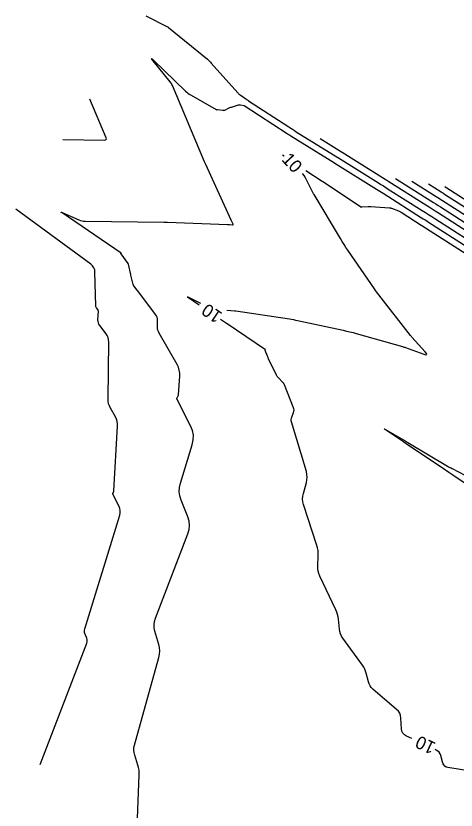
# Model space of a CAD drawing. Extents: x 1797789 to 1803805, y 249066 to 250293.
# Drawn here: x 1797804.6 to 1798010.2, y 249881.5 to 250253 of the extents above; entities that cross this region are included whole.
import ezdxf

# ---------------------------------------------------------------- set-up
doc = ezdxf.new("R2010")
doc.units = 0
doc.layers.add('33', color=7, linetype='Continuous')
doc.layers.add('34', color=7, linetype='Continuous')

msp = doc.modelspace()

# ---------------------------------------------------------------- linework, layer by layer
at = {"layer": '33'}
for points in [[(1797929.68, 250187.48), (1797929.31, 250187.81), (1797929.13, 250187.99), (1797929.08, 250188.07), (1797929.16, 250188.03), (1797929.38, 250187.9), (1797929.81, 250187.61)], [(1797903.13, 250115.46), (1797906.85, 250115.12), (1797906.88, 250115.11), (1797906.92, 250115.11), (1797906.96, 250115.1), (1797907, 250115.1), (1797907.23, 250115.07), (1797907.24, 250115.07), (1797932.35, 250111.26), (1797933.3, 250111.1), (1797934.25, 250110.94), (1797935.19, 250110.76), (1797936.13, 250110.56), (1797957.51, 250105.97), (1797959.03, 250105.62), (1797960.55, 250105.26), (1797962.07, 250104.87), (1797963.58, 250104.45), (1797985.12, 250098.34), (1797985.49, 250098.23), (1797985.86, 250098.12), (1797986.22, 250098), (1797986.59, 250097.87), (1797995.09, 250094.83), (1797996.06, 250094.56), (1797996.5, 250094.65), (1797996.41, 250095.09), (1797995.8, 250095.89), (1797989.57, 250102.82), (1797989.41, 250103), (1797989.25, 250103.18), (1797989.1, 250103.37), (1797988.95, 250103.56), (1797974.11, 250122.5), (1797973.57, 250123.19), (1797973.05, 250123.89), (1797972.54, 250124.59), (1797972.05, 250125.31), (1797959.66, 250143.41), (1797958.76, 250144.75), (1797957.87, 250146.11), (1797957.01, 250147.48), (1797956.17, 250148.86), (1797943.84, 250169.47), (1797943.82, 250169.51), (1797943.81, 250169.54), (1797943.79, 250169.57), (1797943.77, 250169.61), (1797943.65, 250169.81), (1797943.65, 250169.81), (1797939.63, 250177.53), (1797939.17, 250178.33), (1797938.64, 250179.08), (1797938.47, 250179.28)], [(1797940.07, 250180.78), (1797947.6, 250175.77), (1797947.88, 250175.58), (1797947.89, 250175.57), (1797965.96, 250163.53), (1797965.97, 250163.53), (1797965.97, 250163.53), (1797965.97, 250163.53), (1797965.98, 250163.53), (1797966.15, 250163.8), (1797966.16, 250163.8), (1797966.16, 250163.8), (1797966.17, 250163.79), (1797969.12, 250163.84), (1797969.44, 250163.84), (1797969.76, 250163.83), (1797970.07, 250163.82), (1797970.39, 250163.8), (1797979.08, 250163.26), (1797979.32, 250163.24), (1797979.55, 250163.2), (1797979.78, 250163.14), (1797980.01, 250163.06), (1797983.27, 250161.77), (1797983.58, 250161.64), (1797983.89, 250161.49), (1797984.19, 250161.33), (1797984.48, 250161.16), (1797993.86, 250155.21), (1797993.93, 250155.16), (1797994.01, 250155.12), (1797994.08, 250155.07), (1797994.16, 250155.02), (1798014.86, 250141.76)], [(1797989.59, 250175.67), (1798000.85, 250168.54), (1798001.61, 250168.05), (1798002.37, 250167.57), (1798003.13, 250167.08), (1798003.89, 250166.6), (1798020.62, 250155.88), (1798022.02, 250154.98), (1798023.42, 250154.08), (1798024.82, 250153.18), (1798026.22, 250152.27), (1798041.96, 250142.08), (1798043.19, 250141.29), (1798044.41, 250140.49), (1798045.64, 250139.69), (1798046.86, 250138.89), (1798063.61, 250127.93), (1798064.47, 250127.36), (1798065.33, 250126.8), (1798066.19, 250126.23), (1798067.05, 250125.67), (1798084.43, 250114.17), (1798085.23, 250113.64)], [(1797890.22, 250117.79), (1797884.78, 250121.47), (1797884.57, 250121.62), (1797884.51, 250121.69), (1797884.6, 250121.67), (1797884.83, 250121.56), (1797890.84, 250118.72)], [(1797989.48, 249914.97), (1797987.04, 249916.11), (1797986.05, 249916.72), (1797985.33, 249917.51), (1797984.87, 249918.48), (1797984.67, 249919.62), (1797984.4, 249924.56), (1797984.23, 249925.74), (1797983.84, 249926.82), (1797983.23, 249927.78), (1797982.4, 249928.64), (1797971.29, 249938.19), (1797970.57, 249938.9), (1797969.99, 249939.71), (1797969.53, 249940.59), (1797969.22, 249941.56), (1797968.21, 249945.59), (1797967.92, 249946.58), (1797967.53, 249947.52), (1797967.06, 249948.43), (1797966.5, 249949.29), (1797957.32, 249962.01), (1797956.71, 249962.98), (1797956.24, 249964), (1797955.91, 249965.08), (1797955.72, 249966.21), (1797955.25, 249970.84), (1797955.08, 249971.98), (1797954.82, 249973.1), (1797954.47, 249974.19), (1797954.02, 249975.25), (1797946.59, 249991.02), (1797946.14, 249992.14), (1797945.83, 249993.29), (1797945.66, 249994.47), (1797945.64, 249995.68), (1797945.83, 250000.57), (1797945.82, 250001.79), (1797945.71, 250002.99), (1797945.49, 250004.18), (1797945.17, 250005.35), (1797938.95, 250024.51), (1797938.64, 250025.78), (1797938.51, 250027.05), (1797938.58, 250028.33), (1797938.85, 250029.61), (1797940.28, 250034.74), (1797940.54, 250036.02), (1797940.63, 250037.3), (1797940.52, 250038.58), (1797940.24, 250039.85), (1797933.34, 250063.13), (1797933.22, 250063.69), (1797933.19, 250064.25), (1797933.26, 250064.81), (1797933.43, 250065.36), (1797934.27, 250067.56), (1797934.43, 250068.11), (1797934.48, 250068.66), (1797934.43, 250069.21), (1797934.26, 250069.76), (1797930.02, 250080.51), (1797929.92, 250080.74), (1797929.79, 250080.96), (1797929.65, 250081.17), (1797929.48, 250081.36), (1797927.06, 250083.89), (1797926.84, 250084.13), (1797926.65, 250084.39), (1797926.47, 250084.66), (1797926.32, 250084.95), (1797922.61, 250092.63), (1797922.47, 250092.92), (1797922.34, 250093.21), (1797922.22, 250093.5), (1797922.1, 250093.8), (1797921.02, 250096.55), (1797921.02, 250096.55), (1797921.01, 250096.55), (1797921.01, 250096.56), (1797921.01, 250096.56), (1797921.19, 250096.82), (1797921.19, 250096.83), (1797921.19, 250096.83), (1797921.19, 250096.83), (1797921.18, 250096.84), (1797903.2, 250109), (1797902.94, 250109.18), (1797902.91, 250109.2), (1797900.15, 250111.06)], [(1798024.71, 249898.56), (1798006.39, 249901.46), (1798005.56, 249901.7), (1798004.9, 249902.12), (1798004.4, 249902.73), (1798004.07, 249903.53), (1798003.08, 249907.08), (1798002.76, 249907.9), (1798002.29, 249908.6), (1798001.67, 249909.18), (1798000.91, 249909.63), (1798000.35, 249909.89)]]:
    msp.add_lwpolyline(points, dxfattribs=at)
at = {"layer": '34'}
for points in [[(1797865.26, 250253.03), (1797875.33, 250247.98), (1797875.46, 250247.91), (1797875.58, 250247.83), (1797875.71, 250247.75), (1797875.82, 250247.66), (1797894.03, 250232.71), (1797894.51, 250232.3), (1797894.97, 250231.87), (1797895.42, 250231.43), (1797895.85, 250230.96), (1797908.23, 250216.99), (1797908.48, 250216.72), (1797908.74, 250216.48), (1797909.02, 250216.24), (1797909.31, 250216.03), (1797912.4, 250213.9), (1797912.61, 250213.75), (1797912.83, 250213.6), (1797913.04, 250213.46), (1797913.26, 250213.31), (1797932.05, 250201.1), (1797932.92, 250200.53), (1797933.79, 250199.98), (1797934.67, 250199.42), (1797935.54, 250198.87), (1797955.02, 250186.79), (1797955.07, 250186.76), (1797955.24, 250186.65), (1797955.3, 250186.62), (1797955.31, 250186.61), (1797973.94, 250174.92), (1797975.09, 250174.21), (1797976.23, 250173.49), (1797977.37, 250172.76), (1797978.51, 250172.04), (1797994.36, 250162), (1797995.85, 250161.05), (1797997.35, 250160.09), (1797998.85, 250159.14), (1798000.34, 250158.18), (1798016.79, 250147.65)], [(1797861.12, 249869.6), (1797862.22, 249897.86), (1797862.21, 249899.07), (1797862.1, 249900.28), (1797861.88, 249901.46), (1797861.56, 249902.63), (1797860.05, 249907.29), (1797859.76, 249908.46), (1797859.64, 249909.63), (1797859.71, 249910.8), (1797859.95, 249911.98), (1797871.38, 249952.91), (1797871.7, 249954.46), (1797871.8, 249956), (1797871.67, 249957.54), (1797871.33, 249959.08), (1797869.5, 249965.24), (1797869.18, 249966.77), (1797869.11, 249968.3), (1797869.29, 249969.81), (1797869.74, 249971.32), (1797884.88, 250010.79), (1797885.45, 250012.76), (1797885.63, 250014.73), (1797885.43, 250016.7), (1797884.85, 250018.66), (1797881.74, 250026.52), (1797881.14, 250028.49), (1797880.89, 250030.48), (1797880.99, 250032.48), (1797881.44, 250034.49), (1797886.94, 250052.4), (1797887.42, 250054.67), (1797887.45, 250056.89), (1797887.03, 250059.08), (1797886.17, 250061.23), (1797879.88, 250073.58), (1797879.8, 250073.79), (1797879.77, 250074), (1797879.8, 250074.21), (1797879.88, 250074.43), (1797880.52, 250075.65), (1797880.53, 250075.68), (1797880.54, 250075.7), (1797880.54, 250075.72), (1797880.55, 250075.74), (1797880.57, 250075.84), (1797880.58, 250075.86), (1797880.58, 250075.88), (1797880.59, 250075.91), (1797880.59, 250075.93), (1797881.1, 250084.54), (1797881.08, 250085.96), (1797880.86, 250087.34), (1797880.45, 250088.66), (1797879.83, 250089.94), (1797871.45, 250104.65), (1797871.12, 250105.33), (1797870.88, 250106.04), (1797870.74, 250106.77), (1797870.7, 250107.52), (1797870.74, 250110.6), (1797870.69, 250111.35), (1797870.52, 250112.06), (1797870.23, 250112.73), (1797869.83, 250113.36), (1797861.45, 250124.42), (1797861.4, 250124.5), (1797861.34, 250124.57), (1797861.28, 250124.65), (1797861.22, 250124.73), (1797859.64, 250126.79), (1797859.56, 250126.92), (1797859.48, 250127.06), (1797859.42, 250127.2), (1797859.38, 250127.35), (1797858.3, 250131.71), (1797858.24, 250131.96), (1797858.18, 250132.2), (1797858.12, 250132.45), (1797858.07, 250132.7), (1797857.16, 250136.85), (1797857.14, 250136.94), (1797857.1, 250137.03), (1797857.06, 250137.12), (1797857, 250137.2), (1797853.66, 250141.74), (1797853.65, 250141.77), (1797853.64, 250141.8), (1797853.65, 250141.82), (1797853.66, 250141.85), (1797853.8, 250142.06), (1797853.8, 250142.06), (1797853.8, 250142.07), (1797853.8, 250142.08), (1797853.8, 250142.08), (1797826.12, 250160.86), (1797825.74, 250161.13), (1797825.63, 250161.26), (1797825.79, 250161.23), (1797826.23, 250161.06), (1797833.98, 250157.66), (1797834.71, 250157.38), (1797835.45, 250157.18), (1797836.21, 250157.06), (1797836.99, 250157.01), (1797873.73, 250156.58), (1797874.14, 250156.58), (1797874.54, 250156.57), (1797874.94, 250156.56), (1797875.34, 250156.54), (1797903.47, 250155.49), (1797903.69, 250155.48), (1797903.91, 250155.46), (1797904.13, 250155.45), (1797904.35, 250155.43), (1797905.82, 250155.29), (1797905.99, 250155.3), (1797906.08, 250155.36), (1797906.1, 250155.46), (1797906.04, 250155.62), (1797905.23, 250157.18), (1797905.19, 250157.25), (1797905.16, 250157.32), (1797905.12, 250157.4), (1797905.08, 250157.48), (1797893.3, 250183.45), (1797893.16, 250183.77), (1797893.02, 250184.09), (1797892.88, 250184.41), (1797892.74, 250184.73), (1797877.67, 250220.41), (1797877.45, 250220.88), (1797877.2, 250221.33), (1797876.92, 250221.77), (1797876.6, 250222.19), (1797868.67, 250232.07), (1797868.11, 250232.79), (1797867.96, 250233.07), (1797868.22, 250232.9), (1797868.89, 250232.28), (1797883.78, 250217.87), (1797884.34, 250217.36), (1797884.93, 250216.89), (1797885.55, 250216.46), (1797886.19, 250216.06), (1797898.47, 250209.01), (1797898.48, 250209.01), (1797898.49, 250209.01), (1797898.5, 250209.01), (1797898.5, 250209.02), (1797898.64, 250209.22), (1797898.66, 250209.24), (1797898.68, 250209.26), (1797898.71, 250209.27), (1797898.74, 250209.26), (1797901.26, 250208.86), (1797901.49, 250208.84), (1797901.71, 250208.85), (1797901.92, 250208.9), (1797902.13, 250208.99), (1797903.8, 250209.81), (1797904.14, 250209.97), (1797904.5, 250210.12), (1797904.86, 250210.26), (1797905.23, 250210.38), (1797908.49, 250211.36), (1797908.75, 250211.43), (1797909.01, 250211.45), (1797909.28, 250211.45), (1797909.54, 250211.41), (1797911.12, 250211.09), (1797911.13, 250211.09), (1797911.14, 250211.09), (1797911.15, 250211.09), (1797911.16, 250211.08), (1797911.2, 250211.07), (1797911.2, 250211.07), (1797911.21, 250211.07), (1797911.22, 250211.06), (1797911.23, 250211.06), (1797931.25, 250198.04), (1797931.68, 250197.76), (1797932.12, 250197.48), (1797932.55, 250197.2), (1797932.99, 250196.93), (1797953.32, 250184.31), (1797953.37, 250184.29), (1797953.42, 250184.26), (1797953.6, 250184.14), (1797953.62, 250184.13), (1797973.05, 250171.95), (1797973.8, 250171.47), (1797974.56, 250171), (1797975.31, 250170.52), (1797976.07, 250170.04), (1797994.11, 250158.61), (1797994.89, 250158.11), (1797995.68, 250157.61), (1797996.47, 250157.1), (1797997.25, 250156.6), (1798015.83, 250144.7)], [(1797826.41, 250195.16), (1797845.96, 250194.94), (1797846.45, 250195), (1797846.74, 250195.2), (1797846.82, 250195.54), (1797846.69, 250196.02), (1797839.08, 250214.03)], [(1798017.75, 250150.59), (1798001.96, 250160.71), (1798000.49, 250161.65), (1797999.02, 250162.59), (1797997.55, 250163.52), (1797996.08, 250164.46), (1797978.76, 250175.43), (1797978.33, 250175.71), (1797977.9, 250175.98), (1797977.47, 250176.25), (1797977.04, 250176.52), (1797957.01, 250189.08), (1797956.95, 250189.12), (1797956.9, 250189.15), (1797956.71, 250189.27), (1797946.69, 250195.49)], [(1797981.95, 250176.97), (1797998.46, 250166.5), (1797999.58, 250165.79), (1798000.7, 250165.08), (1798001.81, 250164.37), (1798002.92, 250163.65), (1798018.72, 250153.54), (1798020.23, 250152.56), (1798021.75, 250151.59), (1798023.27, 250150.61), (1798024.78, 250149.63), (1798040.74, 250139.3), (1798041.74, 250138.65), (1798042.74, 250138), (1798043.74, 250137.35), (1798044.74, 250136.69), (1798062.25, 250125.23), (1798062.96, 250124.77), (1798063.66, 250124.31), (1798064.36, 250123.85), (1798065.07, 250123.38), (1798083.07, 250111.47), (1798083.57, 250111.15)], [(1798086.9, 250116.14), (1798086.82, 250116.19), (1798085.79, 250116.87), (1798069.03, 250127.95), (1798068.02, 250128.62), (1798067, 250129.29), (1798065.99, 250129.96), (1798064.97, 250130.62), (1798048.98, 250141.09), (1798047.53, 250142.03), (1798046.08, 250142.98), (1798044.63, 250143.92), (1798043.18, 250144.86), (1798027.44, 250155.06), (1798026.27, 250155.81), (1798025.1, 250156.57), (1798023.92, 250157.32), (1798022.75, 250158.07), (1798004.85, 250169.54), (1798004.45, 250169.8), (1798004.04, 250170.06), (1798003.64, 250170.32), (1798003.23, 250170.57), (1797997.24, 250174.38)], [(1798088.57, 250118.63), (1798088.34, 250118.78), (1798087.15, 250119.57), (1798071.02, 250130.24), (1798069.85, 250131.01), (1798068.68, 250131.78), (1798067.51, 250132.55), (1798066.33, 250133.32), (1798050.43, 250143.72), (1798049.09, 250144.6), (1798047.76, 250145.47), (1798046.42, 250146.34), (1798045.07, 250147.21), (1798028.66, 250157.84), (1798027.71, 250158.45), (1798026.77, 250159.06), (1798025.82, 250159.67), (1798024.88, 250160.27), (1798005.81, 250172.49), (1798005.76, 250172.52), (1798005.71, 250172.55), (1798005.67, 250172.58), (1798005.62, 250172.61), (1798004.88, 250173.08)], [(1797815.89, 249902.91), (1797837.67, 249959.7), (1797837.83, 249960.25), (1797837.88, 249960.8), (1797837.83, 249961.35), (1797837.66, 249961.9), (1797836.8, 249964.08), (1797836.63, 249964.63), (1797836.56, 249965.18), (1797836.59, 249965.74), (1797836.71, 249966.3), (1797853.08, 250019.55), (1797853.3, 250020.59), (1797853.31, 250021.61), (1797853.12, 250022.61), (1797852.73, 250023.59), (1797849.84, 250029.25), (1797849.8, 250029.34), (1797849.79, 250029.44), (1797849.8, 250029.54), (1797849.84, 250029.64), (1797850.08, 250030.1), (1797850.11, 250030.16), (1797850.14, 250030.22), (1797850.16, 250030.29), (1797850.18, 250030.35), (1797850.25, 250030.62), (1797850.26, 250030.68), (1797850.28, 250030.75), (1797850.28, 250030.82), (1797850.29, 250030.89), (1797852.07, 250061.1), (1797852.05, 250062.25), (1797851.88, 250063.36), (1797851.54, 250064.43), (1797851.05, 250065.46), (1797848.73, 250069.53), (1797848.22, 250070.56), (1797847.87, 250071.64), (1797847.66, 250072.75), (1797847.6, 250073.9), (1797847.9, 250100.54), (1797847.84, 250101.56), (1797847.61, 250102.54), (1797847.21, 250103.46), (1797846.66, 250104.32), (1797843.75, 250108.17), (1797843.35, 250108.78), (1797843.08, 250109.44), (1797842.93, 250110.13), (1797842.9, 250110.86), (1797843.08, 250114.88), (1797843.06, 250115.11), (1797843.01, 250115.33), (1797842.92, 250115.54), (1797842.79, 250115.74), (1797842.17, 250116.49), (1797842.03, 250116.68), (1797841.93, 250116.89), (1797841.87, 250117.12), (1797841.84, 250117.35), (1797841.5, 250133.15), (1797841.36, 250134.25), (1797840.99, 250135.24), (1797840.4, 250136.1), (1797839.57, 250136.85), (1797804.56, 250162.62)], [(1798024.73, 250027.43), (1798008.69, 250038.21), (1798007.72, 250038.87), (1798006.74, 250039.53), (1798005.76, 250040.19), (1798004.78, 250040.84), (1797986.88, 250052.9), (1797986.44, 250053.2), (1797986, 250053.49), (1797985.56, 250053.79), (1797985.12, 250054.08), (1797977.21, 250059.41), (1797976.71, 250059.76), (1797976.55, 250059.9), (1797976.74, 250059.81), (1797977.28, 250059.51), (1797985.25, 250054.93), (1797985.87, 250054.57), (1797986.48, 250054.21), (1797987.1, 250053.85), (1797987.71, 250053.48), (1798006.14, 250042.38), (1798006.32, 250042.28), (1798006.5, 250042.18), (1798006.69, 250042.08), (1798006.89, 250041.99), (1798007.66, 250041.65), (1798007.86, 250041.57), (1798008.05, 250041.48), (1798008.24, 250041.38), (1798008.42, 250041.28), (1798029.08, 250030.38)]]:
    msp.add_lwpolyline(points, dxfattribs=at)

# ---------------------------------------------------------------- texts
at = {"layer": '33'}
for rotation, p in [(313.143, (1797928.37, 250185.58)), (145.8931, (1797901.43, 250113.83)), (154.9704, (1798001.17, 249912.82))]:
    msp.add_text('10', height=6, rotation=rotation, dxfattribs=at).set_placement(p)

doc.saveas('drawing.dxf')
